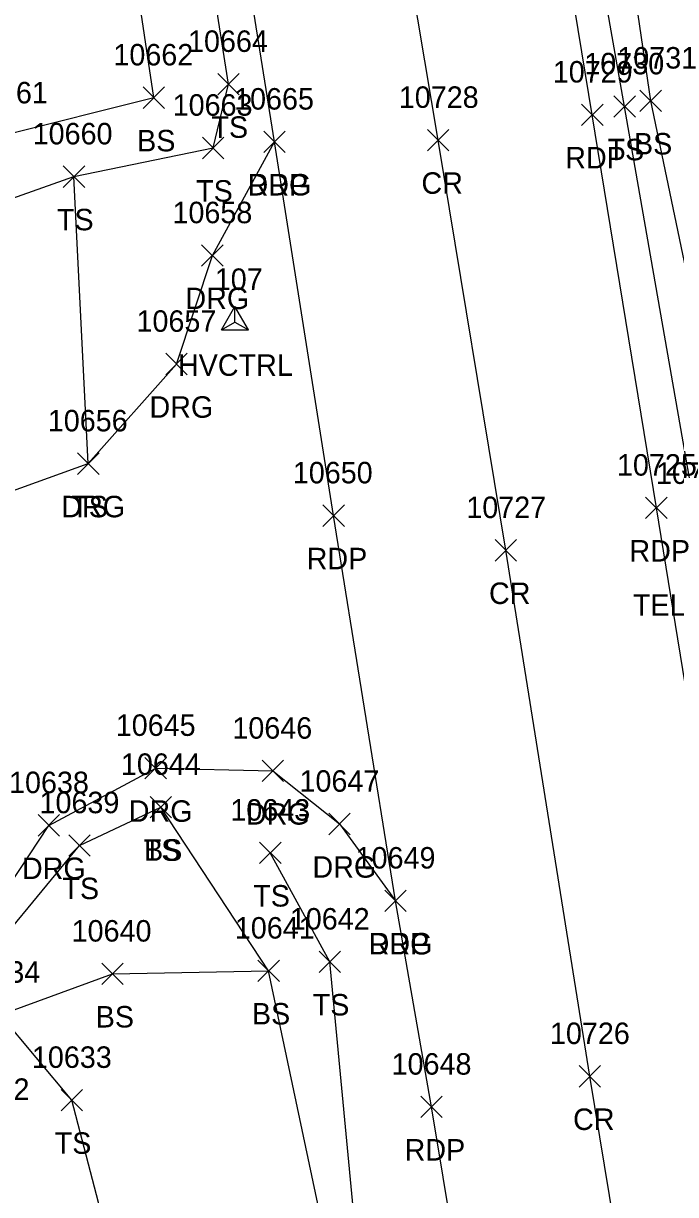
# Model space of a CAD drawing. Extents: x 1439173 to 1457902, y 641926 to 659889.
# Drawn here: x 1448077.2 to 1448137.9, y 647364 to 647473 of the extents above; entities that cross this region are included whole.
import ezdxf

# ---------------------------------------------------------------- set-up
doc = ezdxf.new("R2010")
doc.units = 0
for name, color, linetype in [('C_A', 7, 'Continuous'), ('C_I', 7, 'Continuous'), ('CPSM', 7, 'Continuous'), ('L_A', 7, 'Continuous'), ('L_I', 7, 'Continuous'), ('L_TIC', 7, 'Continuous'), ('LELB', 7, 'Continuous'), ('P_A', 7, 'Continuous'), ('P_I', 7, 'Continuous'), ('P_TIC', 7, 'Continuous'), ('PET', 7, 'Continuous'), ('PRC', 7, 'Continuous'), ('R_A', 7, 'Continuous'), ('R_I', 7, 'Continuous'), ('R_TIC', 7, 'Continuous'), ('RDG', 7, 'Continuous'), ('U_C', 7, 'Continuous')]:
    doc.layers.add(name, color=color, linetype=linetype)

msp = doc.modelspace()

# ---------------------------------------------------------------- linework, layer by layer
at = {"layer": 'CPSM'}
for p, q in [((1448095.66, 647444.49), (1448096.91, 647446.66)), ((1448098.16, 647444.49), (1448096.91, 647446.66)), ((1448096.91, 647445.21), (1448096.91, 647446.66)), ((1448095.66, 647444.49), (1448096.91, 647445.21)), ((1448096.91, 647445.21), (1448096.91, 647445.21)), ((1448096.91, 647445.21), (1448098.16, 647444.49)), ((1448095.66, 647444.49), (1448098.16, 647444.49))]:
    msp.add_line(p, q, dxfattribs=at)
at = {"layer": 'L_TIC'}
for points in [[(1448095.31, 647466.37), (1448097.31, 647468.37)], [(1448097.31, 647466.37), (1448095.31, 647468.37)], [(1448088.36, 647465.11), (1448090.36, 647467.11)], [(1448090.36, 647465.11), (1448088.36, 647467.11)], [(1448132.2, 647464.28), (1448134.2, 647466.28)], [(1448134.2, 647464.28), (1448132.2, 647466.28)], [(1448134.63, 647464.82), (1448136.63, 647466.82)], [(1448136.63, 647464.82), (1448134.63, 647466.82)], [(1448093.88, 647460.43), (1448095.88, 647462.43)], [(1448095.88, 647460.43), (1448093.88, 647462.43)], [(1448080.92, 647457.76), (1448082.92, 647459.76)], [(1448082.92, 647457.76), (1448080.92, 647459.76)], [(1448080.92, 647457.76), (1448082.92, 647459.76)], [(1448082.92, 647457.76), (1448080.92, 647459.76)], [(1448082.25, 647431.04), (1448084.25, 647433.04)], [(1448084.25, 647431.04), (1448082.25, 647433.04)], [(1448089, 647399.06), (1448091, 647401.06)], [(1448091, 647399.06), (1448089, 647401.06)], [(1448089, 647399.06), (1448091, 647401.06)], [(1448091, 647399.06), (1448089, 647401.06)], [(1448081.43, 647395.49), (1448083.43, 647397.49)], [(1448083.43, 647395.49), (1448081.43, 647397.49)], [(1448099.2, 647394.8), (1448101.2, 647396.8)], [(1448101.2, 647394.8), (1448099.2, 647396.8)], [(1448104.74, 647384.66), (1448106.74, 647386.66)], [(1448106.74, 647384.66), (1448104.74, 647386.66)], [(1448084.5, 647383.54), (1448086.5, 647385.54)], [(1448086.5, 647383.54), (1448084.5, 647385.54)], [(1448099.05, 647383.82), (1448101.05, 647385.82)], [(1448101.05, 647383.82), (1448099.05, 647385.82)], [(1448099.05, 647383.82), (1448101.05, 647385.82)], [(1448101.05, 647383.82), (1448099.05, 647385.82)], [(1448080.71, 647371.78), (1448082.71, 647373.78)], [(1448082.71, 647371.78), (1448080.71, 647373.78)]]:
    msp.add_lwpolyline(points, dxfattribs=at)
at = {"layer": 'LELB'}
for points in [[(1448260.6, 647411.18), (1448224.21, 647406.67), (1448190.23, 647399.82), (1448162.27, 647393.34), (1448150.17, 647397.11), (1448143.67, 647427.29), (1448135.63, 647465.82), (1448127.81, 647518.95), (1448121.29, 647557.96), (1448111.76, 647616.1), (1448102.2, 647673.03), (1448093.89, 647725), (1448082.06, 647780.89), (1448072.55, 647837.45), (1448066.89, 647870.13), (1448059.83, 647910.84), (1448057.62, 647927.05), (1448057.68, 647936.79), (1448068.91, 647935.54), (1448077.77, 647925.68)], [(1448069.88, 647454.51), (1448081.92, 647458.76), (1448094.88, 647461.43), (1448096.31, 647467.37), (1448089.21, 647512.69), (1448082.67, 647551.23), (1448072.73, 647610.27), (1448064.94, 647660.74), (1448053.74, 647723.05), (1448045.09, 647774.78), (1448035.51, 647827.8), (1448028.47, 647862.62), (1448021.91, 647904.29), (1448017.86, 647930.03)], [(1448075.24, 647462.58), (1448089.36, 647466.11), (1448082.59, 647511.34), (1448074.74, 647550.35), (1448065.9, 647609.97), (1448055.44, 647658.33)], [(1448260.83, 647409.19), (1448224.69, 647403.55), (1448189.91, 647397.12), (1448162.58, 647390.84), (1448153.24, 647391.75), (1448145.88, 647395.27), (1448139.87, 647427.15), (1448133.2, 647465.28), (1448123.84, 647518.37)], [(1448083.25, 647432.04), (1448081.92, 647458.76)], [(1448120.76, 647212.61), (1448108.79, 647232.5), (1448101.66, 647265.85), (1448091.96, 647303.37), (1448087.69, 647349.91), (1448081.71, 647372.78), (1448075.06, 647380.71), (1448064.59, 647369.24), (1448071.83, 647383.64), (1448082.43, 647396.49), (1448090, 647400.06)], [(1448129.31, 647223.42), (1448127.87, 647230.87), (1448126.04, 647235.76), (1448128.35, 647236.54), (1448122.87, 647269.62), (1448116.31, 647308.01), (1448100.05, 647384.82), (1448090, 647400.06)], [(1448133.3, 647233.02), (1448132.75, 647240.82), (1448128.3, 647270.69), (1448122.37, 647308.82), (1448108.92, 647352.31), (1448105.74, 647385.66), (1448100.2, 647395.8)], [(1448071.38, 647232.61), (1448079.15, 647263.48), (1448079.81, 647303.36), (1448074.35, 647348.2), (1448074.06, 647369.8), (1448075.06, 647380.71), (1448085.5, 647384.54), (1448100.05, 647384.82)]]:
    msp.add_lwpolyline(points, dxfattribs=at)
at = {"layer": 'P_TIC'}
for points in [[(1448129.19, 647463.52), (1448131.19, 647465.52)], [(1448131.19, 647463.52), (1448129.19, 647465.52)], [(1448099.59, 647461), (1448101.59, 647463)], [(1448101.59, 647461), (1448099.59, 647463)], [(1448114.84, 647461.16), (1448116.84, 647463.16)], [(1448116.84, 647461.16), (1448114.84, 647463.16)], [(1448135.16, 647426.92), (1448137.16, 647428.92)], [(1448137.16, 647426.92), (1448135.16, 647428.92)], [(1448105.1, 647426.2), (1448107.1, 647428.2)], [(1448107.1, 647426.2), (1448105.1, 647428.2)], [(1448121.13, 647422.97), (1448123.13, 647424.97)], [(1448123.13, 647422.97), (1448121.13, 647424.97)], [(1448110.87, 647390.34), (1448112.87, 647392.34)], [(1448112.87, 647390.34), (1448110.87, 647392.34)], [(1448128.97, 647374), (1448130.97, 647376)], [(1448130.97, 647374), (1448128.97, 647376)], [(1448114.22, 647371.15), (1448116.22, 647373.15)], [(1448116.22, 647371.15), (1448114.22, 647373.15)]]:
    msp.add_lwpolyline(points, dxfattribs=at)
at = {"layer": 'PET'}
for points in [[(1448210.31, 646953.97), (1448206.09, 646983.02), (1448202.29, 647007.11), (1448197.67, 647036.67), (1448193.54, 647061.45), (1448190, 647087.35), (1448184.11, 647125.89), (1448175.09, 647177.2), (1448170.55, 647212.07), (1448165.67, 647240.9), (1448161.94, 647266.07), (1448155.64, 647304.71), (1448148.08, 647351.45), (1448141.73, 647393.81), (1448136.16, 647427.92), (1448130.19, 647464.52), (1448121.44, 647517.9)], [(1448181.56, 646957.89), (1448177.35, 646983.4), (1448172.19, 647018.8), (1448165.15, 647059.49), (1448161.58, 647085.36), (1448155.74, 647121.99), (1448148.44, 647169.9), (1448145.86, 647185.05), (1448141.04, 647215.97), (1448137.14, 647239.41), (1448132.08, 647270.58), (1448125.76, 647309.48), (1448118.43, 647352.69), (1448115.22, 647372.15), (1448111.87, 647391.34), (1448106.1, 647427.2), (1448100.59, 647462), (1448092.58, 647512.26)]]:
    msp.add_lwpolyline(points, dxfattribs=at)
at = {"layer": 'PRC'}
msp.add_lwpolyline([(1448260.65, 646552.87), (1448253.95, 646593.27), (1448247.21, 646633.9), (1448241.99, 646670.3), (1448235.28, 646711.83), (1448227.36, 646761.05), (1448221.48, 646799.15), (1448208.45, 646883.94), (1448200.39, 646928.86), (1448192.53, 646980.53), (1448184.46, 647032.21), (1448180.05, 647061.28), (1448176.23, 647087.3), (1448169.96, 647123.71), (1448163.11, 647173.92), (1448157.07, 647210.64), (1448152.13, 647238.94), (1448147.96, 647264.25), (1448141.66, 647302.84), (1448134.08, 647349.96), (1448129.97, 647375), (1448122.13, 647423.97), (1448115.84, 647462.16), (1448107.04, 647514.44)], dxfattribs=at)
at = {"layer": 'R_TIC'}
for points in [[(1448099.59, 647461), (1448101.59, 647463)], [(1448101.59, 647461), (1448099.59, 647463)], [(1448093.81, 647450.42), (1448095.81, 647452.42)], [(1448095.81, 647450.42), (1448093.81, 647452.42)], [(1448090.46, 647440.31), (1448092.46, 647442.31)], [(1448092.46, 647440.31), (1448090.46, 647442.31)], [(1448082.25, 647431.04), (1448084.25, 647433.04)], [(1448084.25, 647431.04), (1448082.25, 647433.04)], [(1448088.53, 647402.69), (1448090.53, 647404.69)], [(1448090.53, 647402.69), (1448088.53, 647404.69)], [(1448099.44, 647402.43), (1448101.44, 647404.43)], [(1448101.44, 647402.43), (1448099.44, 647404.43)], [(1448078.58, 647397.36), (1448080.58, 647399.36)], [(1448080.58, 647397.36), (1448078.58, 647399.36)], [(1448105.64, 647397.49), (1448107.64, 647399.49)], [(1448107.64, 647397.49), (1448105.64, 647399.49)], [(1448110.87, 647390.34), (1448112.87, 647392.34)], [(1448112.87, 647390.34), (1448110.87, 647392.34)]]:
    msp.add_lwpolyline(points, dxfattribs=at)
at = {"layer": 'RDG'}
for points in [[(1448045.67, 647383.27), (1448048.73, 647385.21), (1448054.15, 647400.79), (1448062.43, 647417.03), (1448072.14, 647428.04), (1448083.25, 647432.04), (1448091.46, 647441.31), (1448094.81, 647451.42), (1448100.59, 647462)], [(1448066.29, 647375.34), (1448070.49, 647384.61), (1448079.58, 647398.36), (1448089.53, 647403.69), (1448100.44, 647403.43), (1448106.64, 647398.49), (1448111.87, 647391.34)]]:
    msp.add_lwpolyline(points, dxfattribs=at)

# ---------------------------------------------------------------- texts
at = {"layer": 'C_A'}
msp.add_text('HVCTRL', height=2, dxfattribs=at).set_placement((1448091.6, 647440.21))
at = {"layer": 'C_I'}
msp.add_text('107', height=2, dxfattribs=at).set_placement((1448095.03, 647448.21))
at = {"layer": 'L_A'}
for s, p in [('TS', (1448094.72, 647462.37)), ('BS', (1448087.8, 647461.11)), ('BS', (1448134.07, 647460.82)), ('TS', (1448131.61, 647460.28)), ('TS', (1448093.29, 647456.43)), ('TS', (1448080.33, 647453.76)), ('TS', (1448080.33, 647453.76)), ('TS', (1448081.66, 647427.04)), ('TS', (1448088.41, 647395.06)), ('BS', (1448088.44, 647395.06)), ('TS', (1448080.84, 647391.49)), ('TS', (1448098.61, 647390.8)), ('BS', (1448098.49, 647379.82)), ('BS', (1448098.49, 647379.82)), ('TS', (1448104.15, 647380.66)), ('BS', (1448083.94, 647379.54)), ('TS', (1448080.12, 647367.78))]:
    msp.add_text(s, height=2, dxfattribs=at).set_placement(p)
at = {"layer": 'L_I'}
for s, p in [('10664', (1448092.54, 647470.37)), ('10662', (1448085.59, 647469.11)), ('10730', (1448129.45, 647468.28)), ('10731', (1448132.52, 647468.82)), ('10661', (1448072.05, 647465.58)), ('10661', (1448072.05, 647465.58)), ('10663', (1448091.11, 647464.43)), ('10660', (1448078.07, 647461.76)), ('10660', (1448078.07, 647461.76)), ('10656', (1448079.48, 647435.04)), ('10720', (1448136.12, 647430.15)), ('10644', (1448086.29, 647403.06)), ('10644', (1448086.29, 647403.06)), ('10639', (1448078.71, 647399.49)), ('10643', (1448096.48, 647398.8)), ('10642', (1448102.02, 647388.66)), ('10640', (1448081.7, 647387.54)), ('10641', (1448096.9, 647387.82)), ('10641', (1448096.9, 647387.82)), ('10634', (1448071.34, 647383.71)), ('10634', (1448071.34, 647383.71)), ('10633', (1448078, 647375.78)), ('10632', (1448070.34, 647372.8))]:
    msp.add_text(s, height=2, dxfattribs=at).set_placement(p)
at = {"layer": 'P_A'}
for s, p in [('RDP', (1448127.67, 647459.52)), ('RDP', (1448098.08, 647457)), ('CR', (1448114.28, 647457.16)), ('RDP', (1448133.65, 647422.92)), ('RDP', (1448103.59, 647422.2)), ('CR', (1448120.57, 647418.97)), ('RDP', (1448109.36, 647386.34)), ('CR', (1448128.4, 647370)), ('RDP', (1448112.71, 647367.15))]:
    msp.add_text(s, height=2, dxfattribs=at).set_placement(p)
at = {"layer": 'P_I'}
for s, p in [('10729', (1448126.51, 647467.52)), ('10665', (1448096.83, 647465)), ('10728', (1448112.17, 647465.16)), ('10650', (1448102.3, 647430.2)), ('10725', (1448132.49, 647430.92)), ('10727', (1448118.46, 647426.97)), ('10649', (1448108.15, 647394.34)), ('10726', (1448126.25, 647378)), ('10648', (1448111.5, 647375.15))]:
    msp.add_text(s, height=2, dxfattribs=at).set_placement(p)
at = {"layer": 'R_A'}
for p in [(1448098.08, 647457), (1448092.3, 647446.42), (1448088.95, 647436.31), (1448080.74, 647427.04), (1448087.02, 647398.69), (1448097.93, 647398.43), (1448077.07, 647393.36), (1448104.13, 647393.49), (1448109.36, 647386.34)]:
    msp.add_text('DRG', height=2, dxfattribs=at).set_placement(p)
at = {"layer": 'R_I'}
for s, p in [('10665', (1448096.83, 647465)), ('10658', (1448091.09, 647454.42)), ('10657', (1448087.74, 647444.31)), ('10656', (1448079.48, 647435.04)), ('10645', (1448085.81, 647406.69)), ('10646', (1448096.67, 647406.43)), ('10638', (1448075.87, 647401.36)), ('10647', (1448102.92, 647401.49)), ('10649', (1448108.15, 647394.34))]:
    msp.add_text(s, height=2, dxfattribs=at).set_placement(p)
at = {"layer": 'U_C'}
msp.add_text('TEL JCT BOX #23', height=2, dxfattribs=at).set_placement((1448133.97, 647417.87))

doc.saveas('drawing.dxf')
